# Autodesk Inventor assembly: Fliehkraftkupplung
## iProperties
Shininess: 20.0
Angle Display Precision: 2
Document Length Units: 11269
Document Angle Units: 11279
Document Time Units: 11290
Document Mass Units: 11283
Document Length Units Precision: 3
Document Angle Units Precision: 2
Created: 2003-02
Part Number: Fliehkraftkupplung
Document SubType Name: Baugruppe
Designer: Administrator
Density: 0.0
Volumn: 0.0
Area: 0.0
PropertySet Name: Model Information
Control State: 0
Master: False
Checked Out: False
Author: Administrator
